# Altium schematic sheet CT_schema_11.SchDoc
size 387 x 385 mm
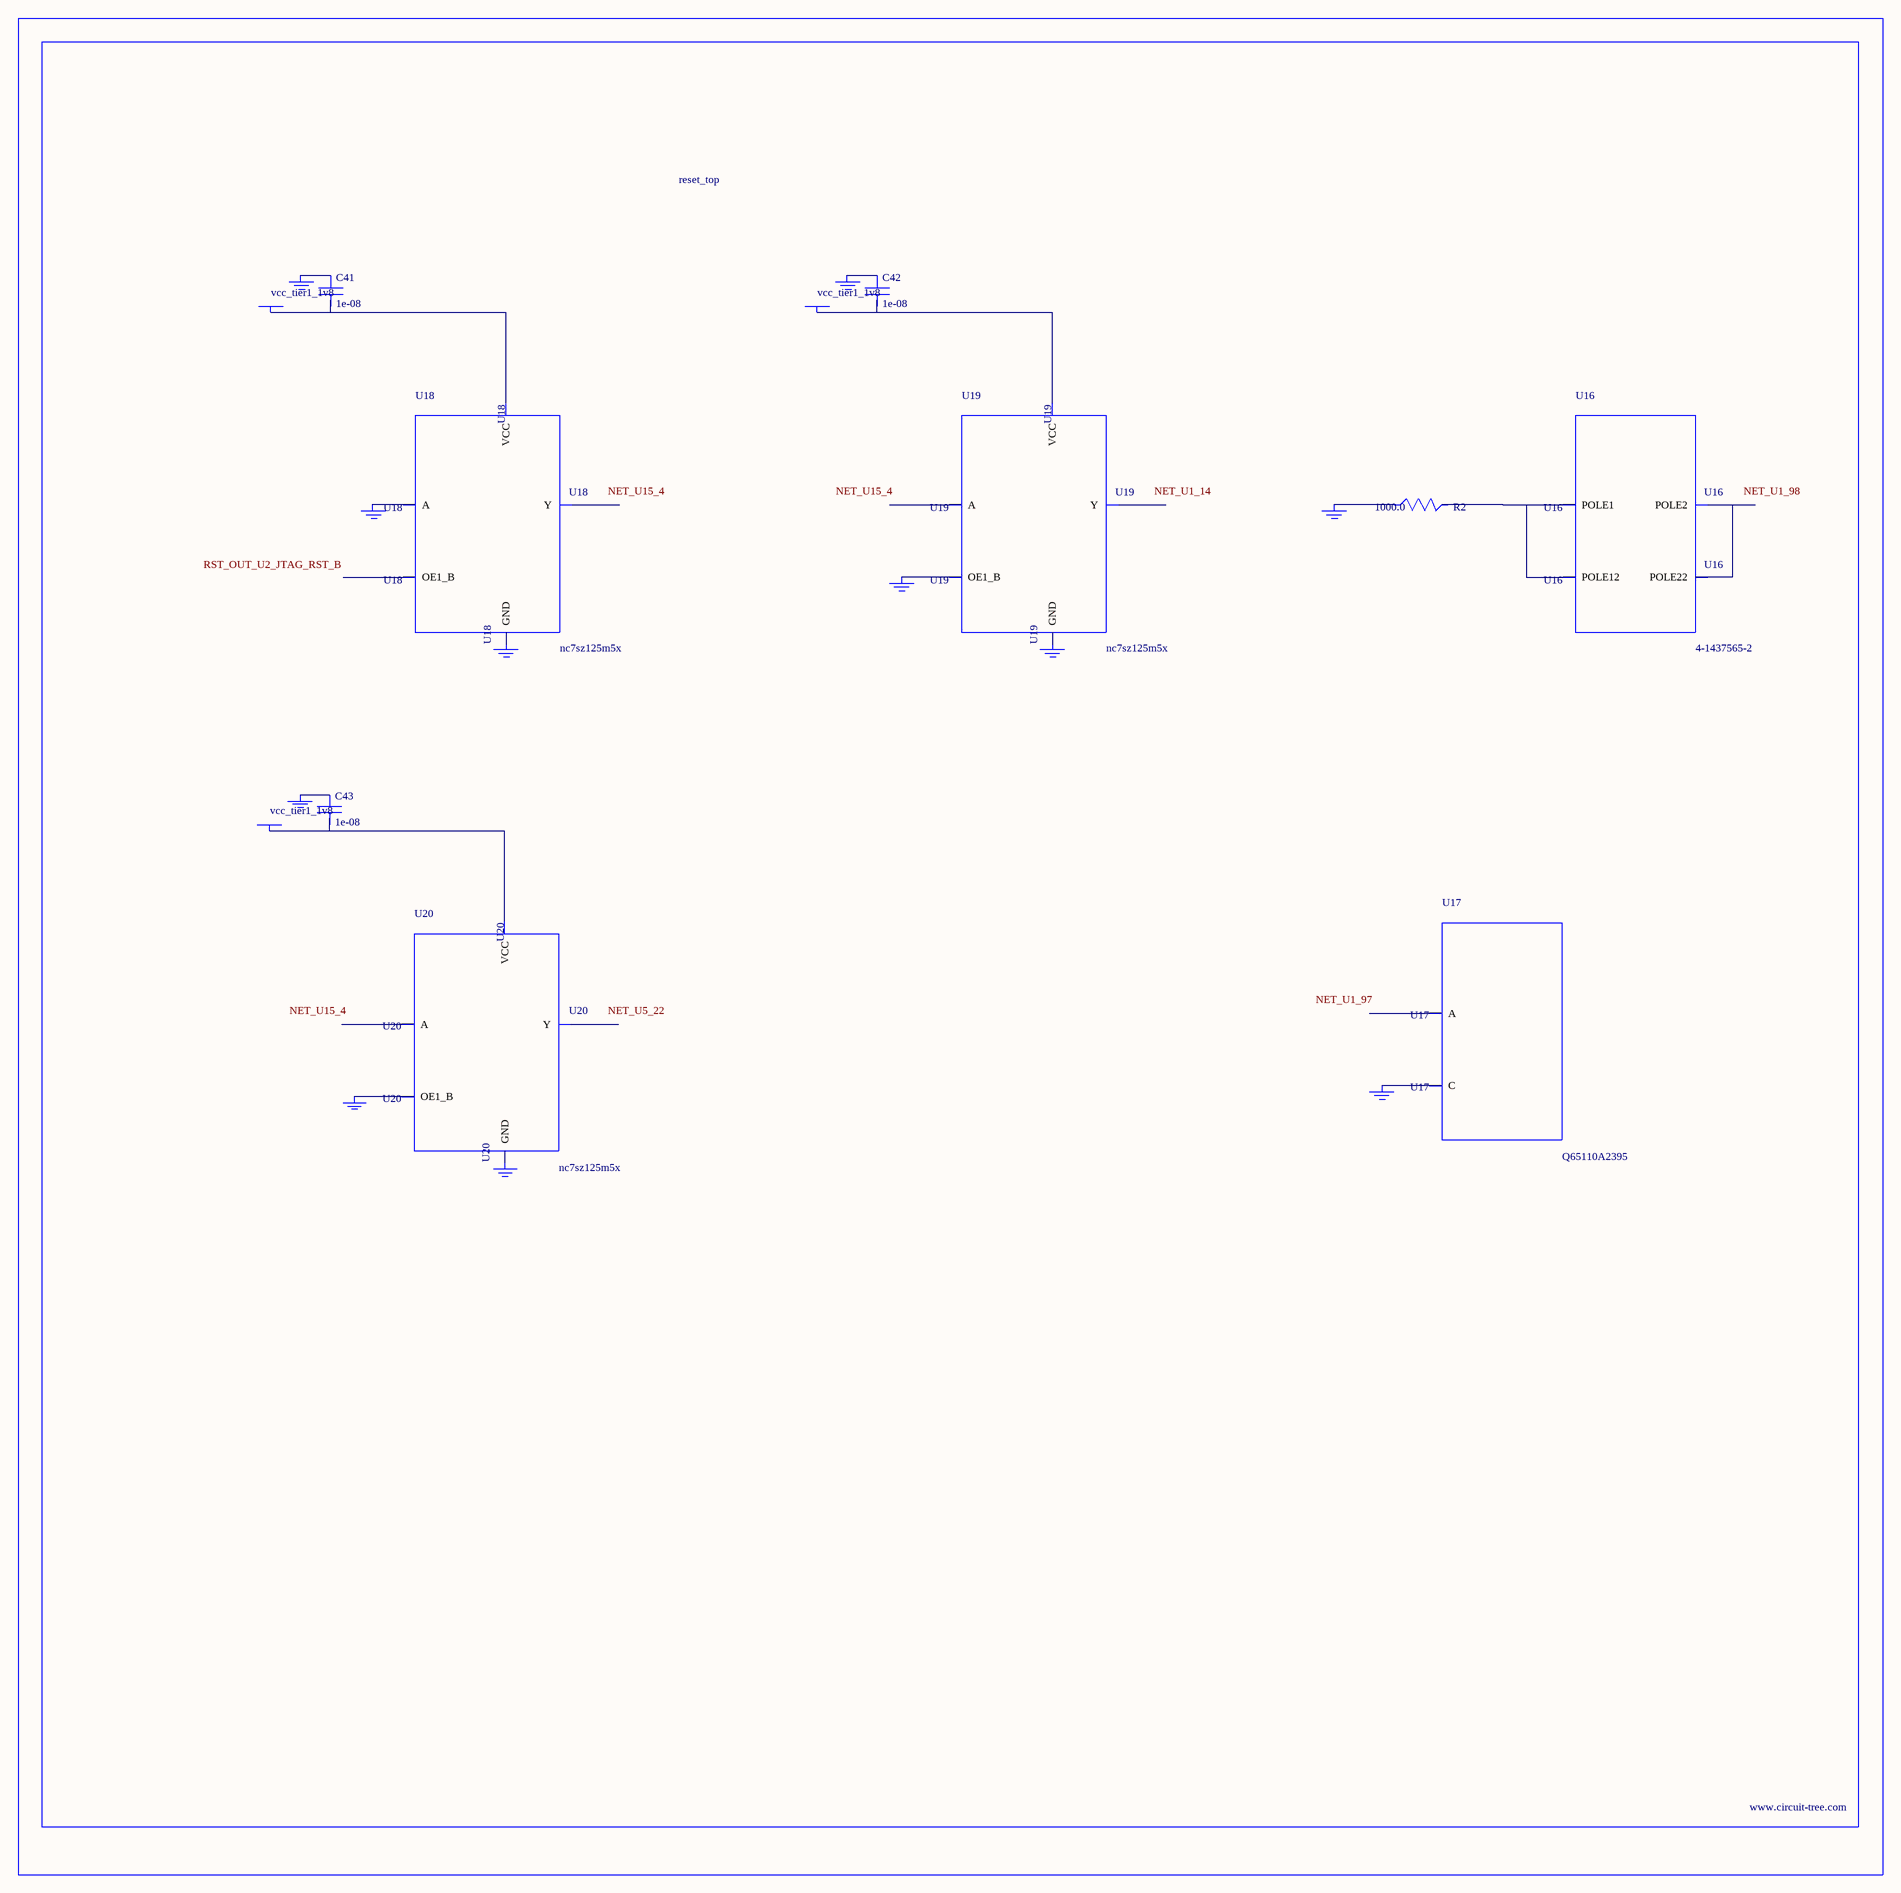
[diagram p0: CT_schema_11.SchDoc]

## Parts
BORDER10  (no value)
C41  1e-08  [C0402]
C42  1e-08  [C0402]
C43  1e-08  [C0402]
GND_INSTANCE_10_0  (no value)
GND_INSTANCE_10_1  (no value)
GND_INSTANCE_10_2  (no value)
GND_INSTANCE_10_3  (no value)
GND_INSTANCE_10_4  (no value)
GND_INSTANCE_10_5  (no value)
GND_INSTANCE_10_6  (no value)
GND_INSTANCE_10_7  (no value)
GND_INSTANCE_10_8  (no value)
GND_INSTANCE_10_9  (no value)
GND_INSTANCE_10_10  (no value)
POWER_INSTANCE_10_0  vcc_tier1_1v8
POWER_INSTANCE_10_1  vcc_tier1_1v8
POWER_INSTANCE_10_2  vcc_tier1_1v8
R2  1000.0  [R0603]
U16  4-1437565-2  [SW_4-1437565-2]
U17  Q65110A2395  [LGM67K-G1J2-24-Z]
U18  nc7sz125m5x  [NC7SZ125M5X]
U19  nc7sz125m5x  [NC7SZ125M5X]
U20  nc7sz125m5x  [NC7SZ125M5X]

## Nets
NetC41_1: C41.1 GND_INSTANCE_10_2.0(GND)
NetC41_2: C41.2 POWER_INSTANCE_10_0.0(PWR) U18.5(VCC)
NetC42_1: C42.1 GND_INSTANCE_10_5.0(GND)
NetC42_2: C42.2 POWER_INSTANCE_10_1.0(PWR) U19.5(VCC)
NetC43_1: C43.1 GND_INSTANCE_10_8.0(GND)
NetC43_2: C43.2 POWER_INSTANCE_10_2.0(PWR) U20.5(VCC)
NetGND_INSTANCE_10_0_0: GND_INSTANCE_10_0.0(GND) R2.1
NetGND_INSTANCE_10_1_0: GND_INSTANCE_10_1.0(GND) U17.C
NetGND_INSTANCE_10_3_0: GND_INSTANCE_10_3.0(GND) U18.2(A)
NetGND_INSTANCE_10_4_0: GND_INSTANCE_10_4.0(GND) U18.3(GND)
NetGND_INSTANCE_10_6_0: GND_INSTANCE_10_6.0(GND) U19.1(OE1_B)
NetGND_INSTANCE_10_7_0: GND_INSTANCE_10_7.0(GND) U19.3(GND)
NetGND_INSTANCE_10_9_0: GND_INSTANCE_10_9.0(GND) U20.1(OE1_B)
NetGND_INSTANCE_10_10_0: GND_INSTANCE_10_10.0(GND) U20.3(GND)
NetR2_2: R2.2 U16.1(POLE1) U16.2(POLE12)
NetU16_3: U16.3(POLE2) U16.4(POLE22)

Not connected (* = marked no-connect by the designer): U17 A; U18 1(OE1_B) 4(Y); U19 2(A) 4(Y); U20 2(A) 4(Y)

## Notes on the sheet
- Labels drawn without touching a wire or pin: NET_U1_14, NET_U1_97, NET_U1_98, NET_U5_22, NET_U15_4, RST_OUT_U2_JTAG_RST_B

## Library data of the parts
BORDER10 = BORDER_PAGE10
C41-C43 = C0402C103K3RAC
GND_INSTANCE_10_0-GND_INSTANCE_10_10 = GND
POWER_INSTANCE_10_0-POWER_INSTANCE_10_2 = PWR
R2 = RC0603JR-071KL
